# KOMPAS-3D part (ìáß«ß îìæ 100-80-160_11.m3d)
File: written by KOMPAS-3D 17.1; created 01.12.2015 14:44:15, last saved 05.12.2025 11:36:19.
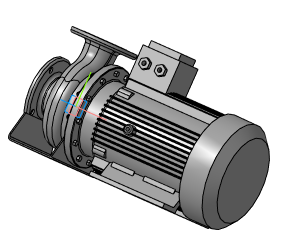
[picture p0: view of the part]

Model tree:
1. Операция без истории:5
